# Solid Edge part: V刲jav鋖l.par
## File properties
Author: Türk
Template: Iso Part.par
Last saved by: Türk
Revision: 11
Application: Solid Edge
Material: Stainless steel
Face Style: Steel
Fill Style: ANSI32(Steel)
Virtual Style: Stainless steel
Coef. of Thermal Exp: 1.6e-05
Thermal Conductivity: 17.0
Specific Heat: 502.0
Modulus of Elasticity: 193053196000.0
Poisson's Ratio: 0.29
Yield Stress: 310264065.0
Ultimate Stress: 641212401.0
Elongation: 0.0
Density: 7750,000 kg/m^3
Accuracy: 0,990
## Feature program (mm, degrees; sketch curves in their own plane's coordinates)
base feature "unnamed BaseFeature 1"
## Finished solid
Body 1: solid body, 25 faces, 48 edges, 24 vertices.
  Faces by surface: plane 15, cylinder 10
  Edges by curve: line 28, circle 20
Bounding box of the edges (mm): 64.000 x 245.000 x 64.000, from (-32, 0, -32) to (32, 245, 32).
Cylindrical faces by radius (mm): R7.5 x2, R10 x4, R14 x1, R15 x2, R32 x1
Planar faces by outward normal: +x 2, +y 4, +z 2, -x 2, -y 3, -z 2
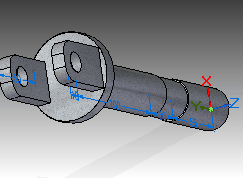
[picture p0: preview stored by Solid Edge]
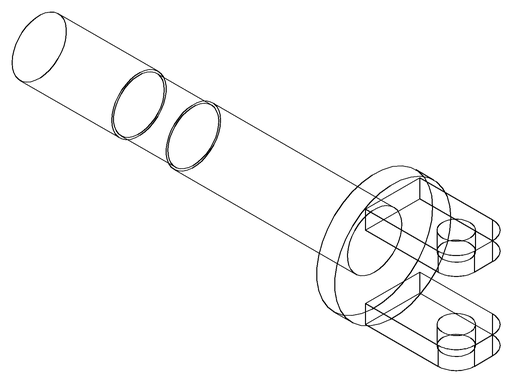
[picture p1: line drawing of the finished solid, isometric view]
